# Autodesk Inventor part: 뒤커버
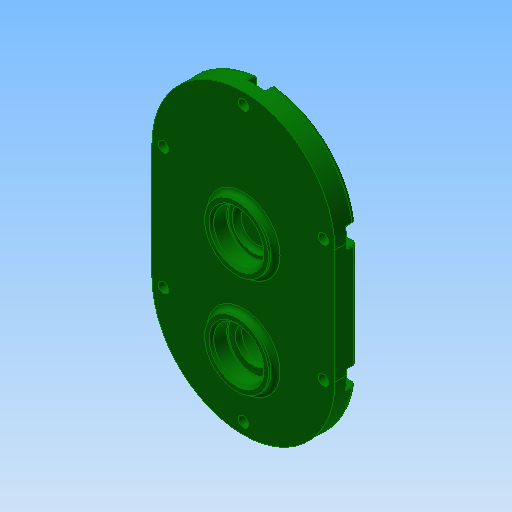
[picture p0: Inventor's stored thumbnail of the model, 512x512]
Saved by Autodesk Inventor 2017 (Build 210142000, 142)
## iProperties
Created: 2016-12
Part Number: 뒤커버
Material: 알루미늄 6061
Document SubType Name: Modeling
Designer: mduedu
Density: 2.71 g/cm^3
Appearance: 진녹색
Mass: 234.724 g
Surface Area: 238.264 cm^2
Volume: 86.614 cm^3
Author: mduedu
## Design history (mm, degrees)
sketch "스케치1"
  geometry: L1 (40, -25)-(40, 25); L2 (-40, 25)-(-40, -25); L3 (-40, -25)-(40, 25); L4 (40, -25)-(-40, 25); A1 r 40 centre (0, 25) between (40, 25) and (-40, 25); A2 r 40 centre (0, -25) between (-40, -25) and (40, -25); 1 further point
  constraints: 8 end point, 4 point on circle, 4 tangent, 2 centre point, 2 midpoint, 1 parallel, 1 vertical
  dimensions: "d0" = 130 dimension on A2 A1; "d2" = 80 distance between parallel lines of L1 L2
extrude "돌출1" new body sketch "스케치1" distance "d3" = 10; taper "d4" = 0 deg
sketch "스케치2"
  geometry: C1 r 14 at (0, 11); 1 further point
  constraints: 1 centre point, 1 vertical alignment
  dimensions: "d5" = 28 diameter of C1; "d6" = 11 distance of C1.centre point (0, 0)
extrude "돌출2" join sketch "스케치2" distance "d7" = 3; taper "d8" = 0 deg
sketch "스케치3"
  geometry: C1 r 14 at (0, -33.1); C2 r 14 at (0, 11) reference; 1 further point
  constraints: 1 centre point, 1 vertical alignment
  dimensions: "d9" = 28 diameter of C1; "d69" = 44.1 distance of C1.centre C2.centre
extrude "돌출3" join sketch "스케치3" distance "d11" = 3; taper "d12" = 0 deg
hole "구멍1" diameter "d15" = 22; stored, may be unused: countersink angle "d19" = 90 deg, drill point angle "d21" = 0 deg; dims "d13" = 10, "d14" = 10, "d16" = 6, "d17" = 4, "d18" = 2, "d20" = 7
hole "구멍2" diameter "d24" = 18; stored, may be unused: countersink angle "d28" = 90 deg, drill point angle "d30" = 0 deg; dims "d25" = 6, "d26" = 4, "d27" = 2, "d29" = 2, "d89" = 10, "d90" = 10
hole "구멍3" diameter "d33" = 22; stored, may be unused: countersink angle "d37" = 90 deg, drill point angle "d39" = 0 deg; dims "d31" = 10, "d32" = 10, "d34" = 6, "d35" = 4, "d36" = 2, "d38" = 7
sketch "스케치4"
  geometry: C1 r 14 at (0, -33.1) reference; C2 r 18 at (0, -33.1); 1 further point
  constraints: 1 centre point, 1 coincident
  dimensions: "d40" = 36 diameter of C2
extrude "돌출4" join sketch "스케치4" distance "d41" = 4; taper "d42" = 0 deg
hole "구멍4" diameter "d45" = 22; stored, may be unused: countersink angle "d49" = 90 deg, drill point angle "d51" = 0 deg; dims "d46" = 6, "d47" = 4, "d48" = 2, "d50" = 7.3, "d84" = 10, "d85" = 10
hole "구멍5" diameter "d54" = 15; stored, may be unused: countersink angle "d58" = 90 deg, drill point angle "d60" = 0 deg; dims "d52" = 10, "d53" = 10, "d55" = 6, "d56" = 4, "d57" = 2, "d59" = 7
fillet "모깎기1" dims "d61" = 0.3
fillet "모깎기2" dims "d62" = 2
chamfer "모따기1" distance "d63" = 0.7; stored, may be unused: second distance "d64" = 2, angle "d65" = 30 deg
fillet "모깎기3" dims "d66" = 2
fillet "모깎기4" dims "d67" = 2
fillet "모깎기5" dims "d68" = 2
sketch "스케치5"
  geometry: L1 (-40, 25)-(-40, -25) reference; L2 (40, -25)-(40, 25) reference; L3 (35, 25)-(35, -25); L4 (-35, -25)-(-35, 25); A1 r 40 centre (0, 25) between (40, 25) and (-40, 25) reference; A2 r 40 centre (0, -25) between (-40, -25) and (40, -25) reference; A3 r 35 centre (0, 25) between (35, 25) and (-35, 25); A4 r 35 centre (0, -25) between (-35, -25) and (35, -25); 2 further points
  constraints: 5 point on circle, 4 end point, 2 centre point, 1 vertical alignment, 3 other
  dimensions: "d70" = 5 distance between parallel lines of L2 L3
sketch "스케치6"
  geometry: 1 further point
hole "구멍6" sketch "스케치6" at (0, 60) diameter "d71" = 4.5; stored, may be unused: countersink angle "d75" = 90 deg, drill point angle "d77" = 0 deg; dims "d72" = 6, "d73" = 8, "d74" = 4.6, "d76" = 8
sketch "스케치7"
  geometry: L1 (-4, 0)-(4, 0); L2 (4, 0)-(4, 5); L3 (4, 5)-(-4, 5); L4 (-4, 5)-(-4, 0); C1 r 2.25 at (0, 0) reference; A1 r 40 centre (0, -35) between (40, -35) and (-40, -35) reference; 2 further points
  constraints: 8 end point, 2 parallel, 2 vertical, 1 horizontal, 1 horizontal alignment, 1 perpendicular, 1 tangent, 1 other
extrude "돌출5" cut sketch "스케치7" stored distance "d80" = 10; taper "d81" = 0 deg
fillet "모깎기6" dims "d82" = 0.3
fillet "모깎기7" dims "d83" = 0.3
chamfer "모따기2" distance "d86" = 1; stored, may be unused: second distance "d87" = 2, angle "d88" = 45 deg
node "솔리드1"
pattern_linear "직사각형 패턴1"
node "투영된 루프1"
